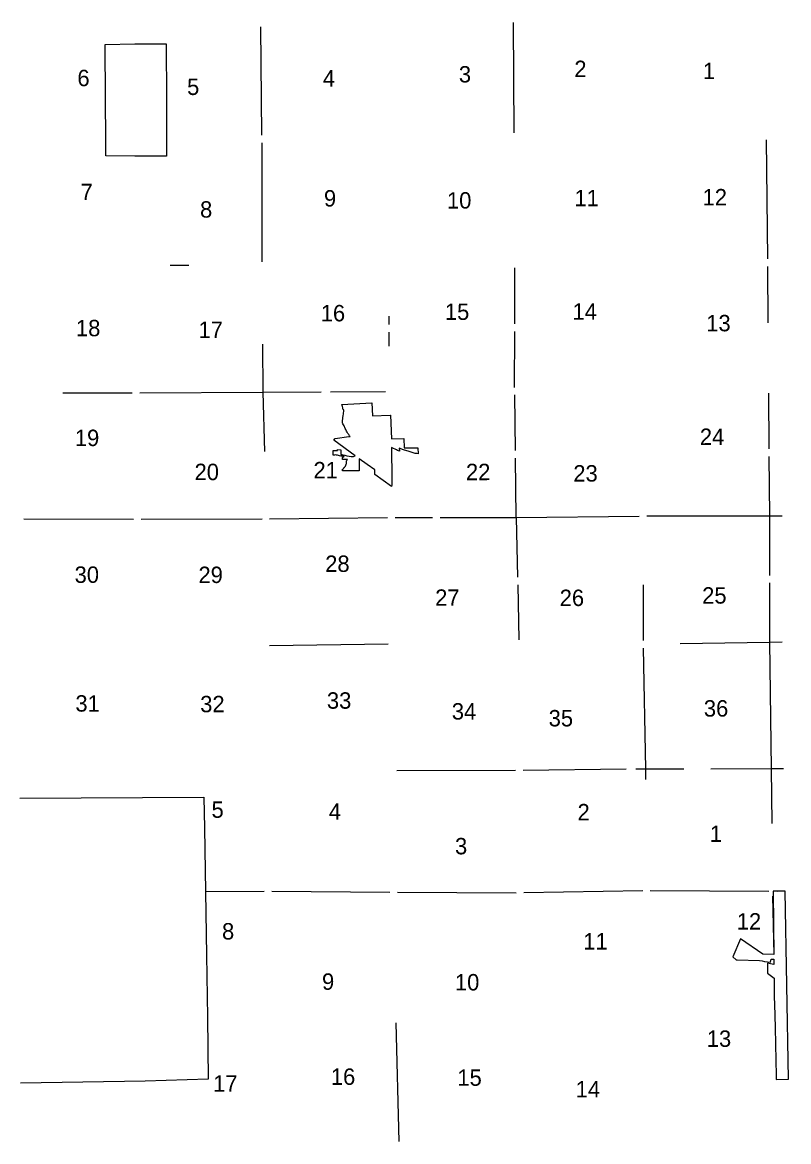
# Model space of a CAD drawing. Extents: x -2933025 to 31692252, y -2344676 to 23854604.
# Drawn here: x -2156022 to -2123980, y -2146614 to -2099809 of the extents above; entities that cross this region are included whole.
import ezdxf

# ---------------------------------------------------------------- set-up
doc = ezdxf.new("R2010")
doc.units = 0
for name, color, linetype in [('tdCoCorpBndry', 7, 'Continuous'), ('tdCoSectLinePart', 7, 'Continuous'), ('tdCoSectNmbr', 7, 'Continuous')]:
    doc.layers.add(name, color=color, linetype=linetype)

msp = doc.modelspace()

# ---------------------------------------------------------------- linework, layer by layer
at = {"layer": 'tdCoCorpBndry'}
for points in [[(-2152561, -2100727), (-2151325, -2100699), (-2150011, -2100708), (-2149999, -2103020), (-2149991, -2104684), (-2149990, -2105410), (-2151313, -2105402), (-2152537, -2105394), (-2152539, -2104693), (-2152543, -2103030), (-2152543, -2103013), (-2152543, -2103005)], [(-2142666, -2115783), (-2141408, -2115719), (-2141379, -2116263), (-2140644, -2116239), (-2140626, -2116238), (-2140592, -2117218), (-2140067, -2117215), (-2140062, -2117605), (-2139480, -2117607), (-2139478, -2117850), (-2139522, -2117844), (-2139599, -2117832), (-2139724, -2117800), (-2139842, -2117760), (-2140078, -2117678), (-2140259, -2117612), (-2140258, -2117738), (-2140329, -2117710), (-2140373, -2117690), (-2140433, -2117662), (-2140496, -2117632), (-2140593, -2117587), (-2140586, -2117986), (-2140586, -2118038), (-2140573, -2118469), (-2140568, -2118842), (-2140570, -2119171), (-2140582, -2119195), (-2140591, -2119220), (-2141283, -2118721), (-2141285, -2118521), (-2141601, -2118303), (-2141940, -2118058), (-2141932, -2118557), (-2142634, -2118561), (-2142634, -2118499), (-2142617, -2118487), (-2142601, -2118476), (-2142586, -2118460), (-2142573, -2118443), (-2142559, -2118426), (-2142545, -2118409), (-2142533, -2118391), (-2142517, -2118370), (-2142509, -2118354), (-2142499, -2118334), (-2142490, -2118311), (-2142485, -2118294), (-2142480, -2118280), (-2142473, -2118259), (-2142473, -2118233), (-2142469, -2118193), (-2142462, -2118155), (-2142452, -2118119), (-2142429, -2118090), (-2142633, -2118091), (-2142632, -2118005), (-2142572, -2117953), (-2142710, -2117953), (-2142765, -2117932), (-2142845, -2117904), (-2142861, -2117902), (-2142890, -2117903), (-2142935, -2117900), (-2142970, -2117903), (-2142995, -2117904), (-2143019, -2117905), (-2143019, -2117885), (-2143019, -2117719), (-2142842, -2117718), (-2142842, -2117677), (-2142706, -2117679), (-2142708, -2117873), (-2142661, -2117878), (-2142618, -2117887), (-2142538, -2117904), (-2142450, -2117929), (-2142361, -2117947), (-2142271, -2117960), (-2142181, -2117964), (-2142110, -2117938), (-2143001, -2117283), (-2142943, -2117214), (-2142366, -2117133), (-2142316, -2117125), (-2142343, -2117102), (-2142375, -2117046), (-2142408, -2117007), (-2142443, -2116946), (-2142470, -2116902), (-2142482, -2116867), (-2142503, -2116829), (-2142524, -2116787), (-2142540, -2116756), (-2142549, -2116724), (-2142551, -2116702), (-2142571, -2116684), (-2142591, -2116641), (-2142618, -2116593), (-2142631, -2116554), (-2142636, -2116516), (-2142640, -2116477), (-2142634, -2116434), (-2142625, -2116398), (-2142616, -2116337), (-2142604, -2116259), (-2142597, -2116175), (-2142589, -2116142), (-2142580, -2116088), (-2142576, -2116043), (-2142580, -2116015), (-2142601, -2115992), (-2142622, -2115973), (-2142628, -2115933), (-2142637, -2115870), (-2142654, -2115826)], [(-2123980, -2144006), (-2124125, -2136147), (-2124629, -2136147), (-2124615, -2137535), (-2124602, -2138787), (-2125055, -2138779), (-2125991, -2138130), (-2126318, -2138885), (-2126177, -2139009), (-2126127, -2139014), (-2125201, -2139039), (-2125087, -2139058), (-2124983, -2139075), (-2124740, -2139115), (-2124716, -2138981), (-2124599, -2138987), (-2124596, -2139207), (-2124736, -2139176), (-2124865, -2139153), (-2124858, -2139567), (-2124586, -2139779), (-2124585, -2139819), (-2124581, -2140424), (-2124566, -2141014), (-2124561, -2141205), (-2124557, -2141375), (-2124544, -2141811), (-2124525, -2142569), (-2124512, -2143186), (-2124498, -2143878), (-2124495, -2144014)]]:
    msp.add_lwpolyline(points, close=True, dxfattribs=at)
msp.add_lwpolyline([(-2156133, -2132258), (-2148430, -2132212), (-2148409, -2133500), (-2148319, -2138819), (-2148276, -2141412), (-2148249, -2144004), (-2150881, -2144088), (-2156098, -2144176)], dxfattribs=at)
at = {"layer": 'tdCoSectLinePart'}
for points in [[(-2146013, -2104525), (-2146050, -2099999)], [(-2135499, -2099809), (-2135470, -2104432)], [(-2124918, -2104723), (-2124862, -2109696)], [(-2146011, -2104841), (-2146010, -2109821)], [(-2149846, -2109958), (-2149068, -2109962)], [(-2135435, -2112418), (-2135434, -2110075)], [(-2124859, -2110012), (-2124845, -2112377)], [(-2140699, -2112099), (-2140697, -2112443)], [(-2140695, -2112760), (-2140692, -2113352)], [(-2135436, -2115073), (-2135435, -2112734)], [(-2145981, -2113260), (-2145963, -2115275)], [(-2154325, -2115295), (-2151427, -2115303)], [(-2151110, -2115302), (-2145963, -2115275)], [(-2145963, -2115275), (-2143533, -2115257)], [(-2145963, -2115275), (-2145904, -2117755)], [(-2143136, -2115254), (-2140841, -2115238)], [(-2135407, -2117714), (-2135434, -2115390)], [(-2124827, -2115313), (-2124807, -2117646)], [(-2135375, -2120518), (-2135403, -2118031)], [(-2124804, -2117964), (-2124783, -2120446)], [(-2155960, -2120574), (-2151372, -2120577)], [(-2151056, -2120577), (-2146002, -2120573)], [(-2145685, -2120571), (-2140751, -2120514)], [(-2140434, -2120512), (-2138876, -2120514)], [(-2138556, -2120514), (-2135375, -2120518)], [(-2135375, -2120518), (-2130231, -2120452)], [(-2135375, -2120518), (-2135316, -2123011)], [(-2129912, -2120450), (-2124783, -2120446)], [(-2124783, -2120446), (-2124255, -2120444)], [(-2124783, -2120446), (-2124783, -2122933)], [(-2135309, -2123327), (-2135255, -2125633)], [(-2130065, -2123335), (-2130059, -2125662)], [(-2124784, -2123253), (-2124784, -2125721)], [(-2145692, -2125871), (-2140722, -2125799)], [(-2128513, -2125790), (-2124784, -2125721)], [(-2124784, -2125721), (-2124256, -2125720)], [(-2124784, -2125721), (-2124714, -2131016)], [(-2130056, -2125978), (-2129969, -2131021)], [(-2135080, -2131074), (-2130779, -2131029)], [(-2130371, -2131025), (-2129969, -2131021)], [(-2129969, -2131021), (-2128357, -2131019)], [(-2129969, -2131021), (-2129965, -2131472)], [(-2127226, -2131018), (-2124714, -2131016)], [(-2124714, -2131016), (-2124190, -2131015)], [(-2124714, -2131016), (-2124687, -2133306)], [(-2140369, -2131091), (-2135396, -2131076)], [(-2148366, -2136153), (-2145908, -2136137)], [(-2145592, -2136138), (-2140657, -2136186)], [(-2135051, -2136203), (-2130083, -2136117)], [(-2129766, -2136115), (-2124801, -2136140)], [(-2124443, -2136136), (-2124126, -2136132)], [(-2140340, -2136189), (-2135368, -2136211)], [(-2124650, -2136355), (-2124605, -2138787)], [(-2124602, -2138987), (-2124601, -2139044)], [(-2140408, -2141647), (-2140286, -2146614)]]:
    msp.add_lwpolyline(points, dxfattribs=at)

# ---------------------------------------------------------------- texts
at = {"layer": 'tdCoSectNmbr'}
for s, height, rotation, p in [('2', 686, 0.0207, (-2132941, -2102096)), ('1', 686, 0.0214, (-2127561, -2102180)), ('6', 686, 0.0176, (-2153721, -2102477)), ('4', 686, 0.0191, (-2143459, -2102491)), ('3', 686, 0.02, (-2137769, -2102322)), ('5', 686, 0.0183, (-2149135, -2102845)), ('7', 686, 0.0176, (-2153585, -2107242)), ('9', 686, 0.0191, (-2143411, -2107509)), ('10', 686.4, 0.0198, (-2138266, -2107596)), ('11', 686.4, 0.0205, (-2132935, -2107499)), ('12', 686.4, 0.0213, (-2127579, -2107462)), ('8', 686, 0.0183, (-2148592, -2107973)), ('16', 686.4, 0.0189, (-2143546, -2112312)), ('15', 686.4, 0.0197, (-2138354, -2112252)), ('14', 686.4, 0.0205, (-2133019, -2112242)), ('18', 686.4, 0.0174, (-2153782, -2112935)), ('13', 686.4, 0.0213, (-2127424, -2112728)), ('17', 686.4, 0.0182, (-2148657, -2113006)), ('19', 686.4, 0.0173, (-2153828, -2117527)), ('24', 686.4, 0.0211, (-2127691, -2117480)), ('20', 686.4, 0.0181, (-2148823, -2118951)), ('21', 686.4, 0.0187, (-2143849, -2118876)), ('22', 686.4, 0.0203, (-2137474, -2118953)), ('23', 686.4, 0.0203, (-2132983, -2119011)), ('28', 686.4, 0.0187, (-2143359, -2122790)), ('30', 686.4, 0.0172, (-2153838, -2123247)), ('29', 686.4, 0.0179, (-2148660, -2123255)), ('27', 686.4, 0.0193, (-2138761, -2124207)), ('26', 686.4, 0.0203, (-2133553, -2124216)), ('25', 686.4, 0.021, (-2127595, -2124116)), ('31', 686.4, 0.0171, (-2153804, -2128632)), ('32', 686.4, 0.0179, (-2148586, -2128659)), ('33', 686.4, 0.0186, (-2143287, -2128510)), ('36', 686.4, 0.0209, (-2127524, -2128840)), ('34', 686.4, 0.0194, (-2138064, -2128964)), ('35', 686.4, 0.02, (-2134014, -2129251)), ('5', 686, 0.0178, (-2148113, -2133072)), ('4', 686, 0.0185, (-2143206, -2133150)), ('2', 686, 0.02, (-2132806, -2133179)), ('1', 686, 0.0208, (-2127275, -2134082)), ('3', 686, 0.0193, (-2137930, -2134600)), ('12', 686.4, 0.0207, (-2126148, -2137747)), ('8', 686, 0.0177, (-2147673, -2138161)), ('11', 686.4, 0.0199, (-2132569, -2138581)), ('9', 686, 0.0185, (-2143492, -2140265)), ('10', 686.4, 0.0192, (-2137934, -2140292)), ('13', 686.4, 0.0206, (-2127402, -2142652)), ('16', 686.4, 0.0183, (-2143123, -2144241)), ('15', 686.4, 0.0191, (-2137832, -2144280)), ('17', 686.4, 0.0176, (-2148046, -2144529)), ('14', 686.4, 0.0198, (-2132884, -2144766))]:
    msp.add_text(s, height=height, rotation=rotation, dxfattribs=at).set_placement(p)

doc.saveas('drawing.dxf')
